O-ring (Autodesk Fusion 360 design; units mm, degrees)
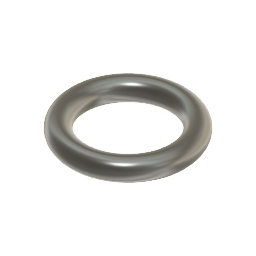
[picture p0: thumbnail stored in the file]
part number: 2025-12-16-11-03-49-491
sketch "Sketch1" plane through (0, 0, 0) normal (0, 1, 0) x axis (1, 0, 0)
  line L1 (0, -31.5008) -> (0, 0)
  circle C1 centre (6, 0) radius 1.25
  point P1 (0, 0)
  point P2 (0, 0)
  point P4 (6, 0)
  coincident P1 P2
  vertical L1
  horizontal P1 P4
  dimension "d1" diameter C1 = 2.5
  dimension "d2" = 12
revolve "Revolve1" sketch "Sketch1" AlongAngle 360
